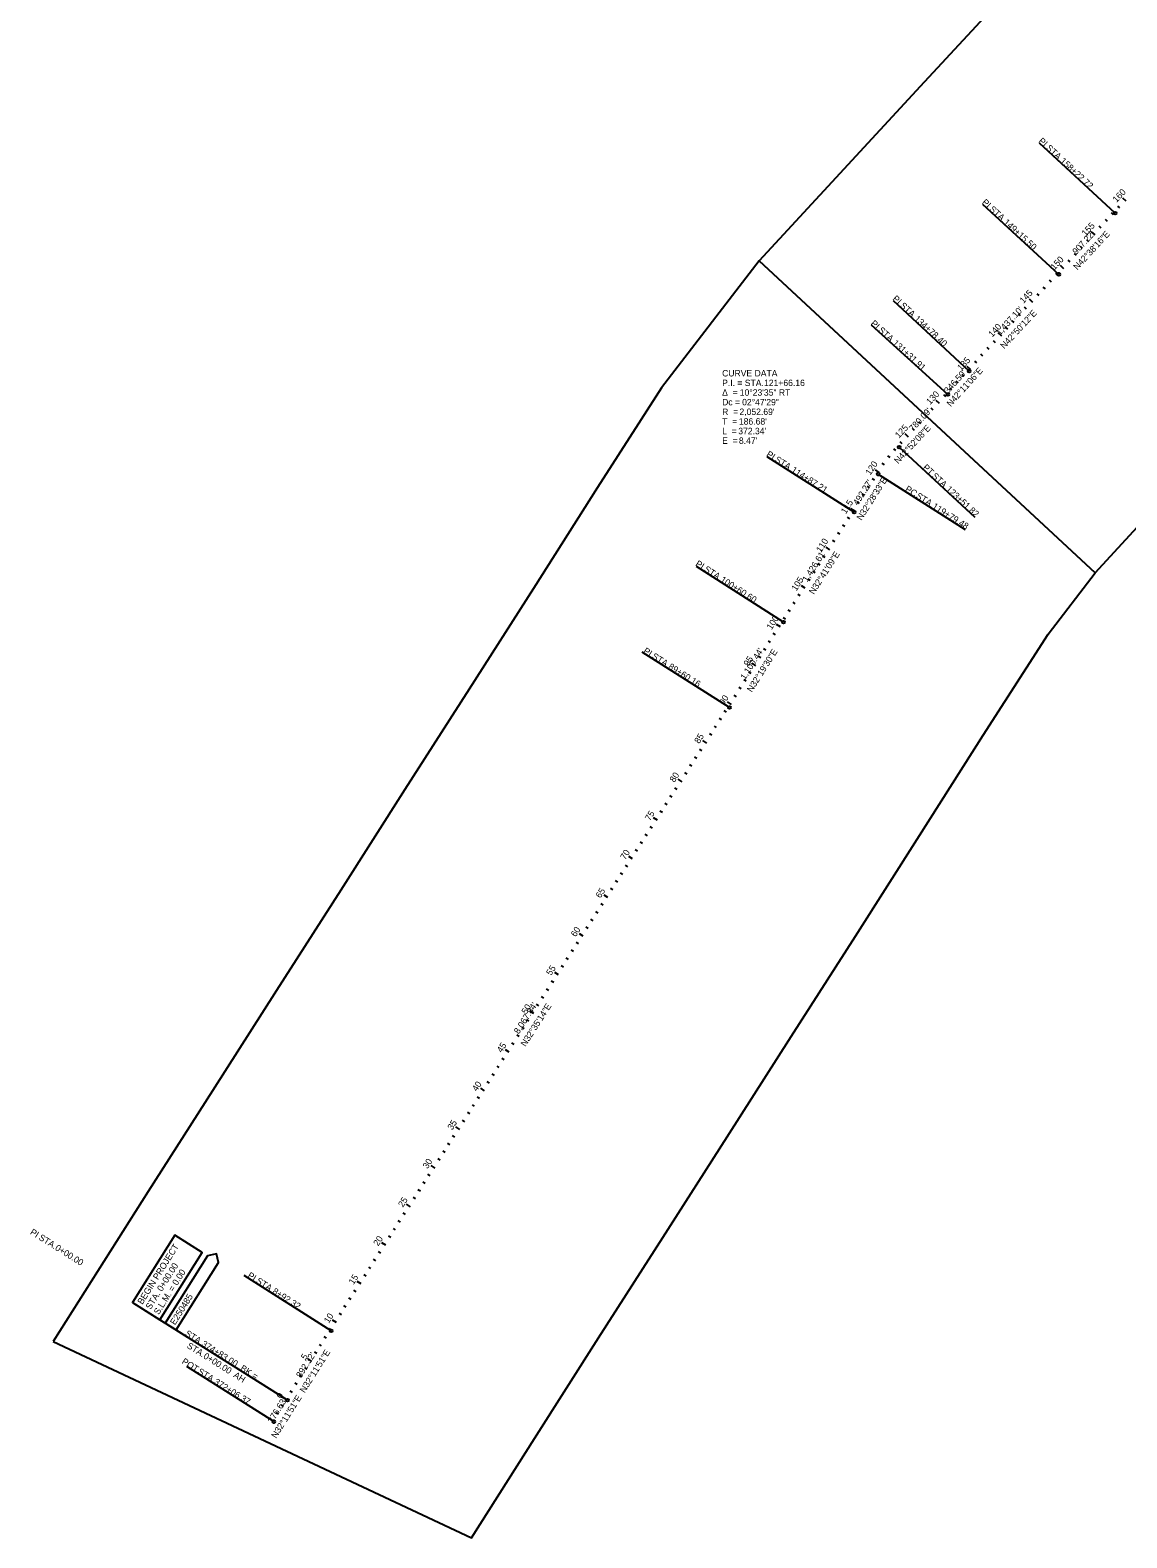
# Model space of a CAD drawing. Extents: x 187058 to 230449, y 263308 to 297406.
# Drawn here: x 187058 to 199019, y 263308 to 279748 of the extents above; entities that cross this region are included whole.
import ezdxf

# ---------------------------------------------------------------- set-up
doc = ezdxf.new("R2010")
doc.units = 0
for name, color, linetype in [('BR_X_Gen_Approach_Slab', 7, 'Continuous'), ('BR_X_SV_Deck_Top', 7, 'Continuous'), ('PV_X_Curb', 7, 'Continuous'), ('PV_X_Walk', 7, 'Continuous'), ('RD_X_GR_Lt', 7, 'Continuous'), ('SH_Named_Boundary', 7, 'Continuous')]:
    doc.layers.add(name, color=color, linetype=linetype)

msp = doc.modelspace()

# ---------------------------------------------------------------- linework, layer by layer
at = {"layer": 'BR_X_SV_Deck_Top'}
for p, q in [((199011, 277882), (198974, 277916)), ((198807, 277662), (198785, 277682)), ((198875, 277735), (198853, 277756)), ((198943, 277809), (198921, 277829)), ((198672, 277515), (198635, 277549)), ((198740, 277588), (198718, 277609)), ((198536, 277368), (198514, 277388)), ((198604, 277441), (198582, 277461)), ((198333, 277147), (198296, 277181)), ((198401, 277220), (198379, 277241)), ((198469, 277294), (198447, 277314)), ((198198, 277000), (198176, 277020)), ((198265, 277073), (198243, 277094)), ((198062, 276853), (198040, 276874)), ((198130, 276927), (198108, 276947)), ((197926, 276707), (197904, 276727)), ((197994, 276780), (197957, 276814)), ((197790, 276560), (197768, 276580)), ((197858, 276633), (197836, 276654)), ((197586, 276340), (197564, 276360)), ((197654, 276413), (197617, 276447)), ((197722, 276487), (197700, 276507)), ((197450, 276193), (197428, 276214)), ((197518, 276267), (197496, 276287)), ((197314, 276047), (197277, 276081)), ((197382, 276120), (197360, 276140)), ((197179, 275899), (197157, 275919)), ((197246, 275973), (197224, 275993)), ((196977, 275677), (196940, 275711)), ((197045, 275751), (197023, 275771)), ((197112, 275825), (197090, 275845)), ((196840, 275531), (196818, 275551)), ((196908, 275604), (196886, 275625)), ((196704, 275384), (196682, 275405)), ((196772, 275458), (196750, 275478)), ((196568, 275238), (196546, 275258)), ((196636, 275311), (196600, 275345)), ((196436, 275087), (196413, 275106)), ((196501, 275164), (196478, 275184)), ((196319, 274925), (196277, 274953)), ((196376, 275008), (196352, 275025)), ((196212, 274757), (196187, 274773)), ((196266, 274841), (196240, 274857)), ((196105, 274588), (196079, 274604)), ((196158, 274672), (196133, 274688)), ((195997, 274419), (195972, 274436)), ((196051, 274504), (196009, 274530)), ((195889, 274251), (195864, 274267)), ((195943, 274335), (195918, 274351)), ((195781, 274083), (195739, 274110)), ((195835, 274167), (195810, 274183)), ((195673, 273914), (195648, 273931)), ((195727, 273999), (195702, 274015)), ((195565, 273746), (195540, 273762)), ((195619, 273830), (195594, 273846)), ((195457, 273578), (195432, 273594)), ((195511, 273662), (195469, 273689)), ((195349, 273409), (195324, 273426)), ((195403, 273494), (195378, 273510)), ((195241, 273241), (195199, 273268)), ((195295, 273325), (195270, 273341)), ((195134, 273072), (195109, 273088)), ((195188, 273156), (195162, 273172)), ((195027, 272903), (195002, 272919)), ((195081, 272987), (195055, 273003)), ((194920, 272734), (194895, 272750)), ((194974, 272818), (194932, 272845)), ((194813, 272565), (194788, 272581)), ((194867, 272649), (194841, 272665)), ((194706, 272396), (194664, 272423)), ((194760, 272480), (194735, 272496)), ((194653, 272312), (194627, 272328)), ((194545, 272143), (194520, 272159)), ((194599, 272227), (194574, 272243)), ((194437, 271975), (194395, 272001)), ((194491, 272059), (194466, 272075)), ((194330, 271806), (194304, 271822)), ((194383, 271890), (194358, 271906)), ((194222, 271637), (194197, 271654)), ((194276, 271722), (194250, 271738)), ((194114, 271469), (194089, 271485)), ((194168, 271553), (194126, 271580)), ((194006, 271300), (193981, 271317)), ((194060, 271385), (194035, 271401)), ((193899, 271132), (193857, 271159)), ((193953, 271216), (193927, 271232)), ((193791, 270963), (193766, 270980)), ((193845, 271048), (193820, 271064)), ((193683, 270795), (193658, 270811)), ((193737, 270879), (193712, 270895)), ((193576, 270626), (193550, 270643)), ((193629, 270711), (193587, 270738)), ((193468, 270458), (193443, 270474)), ((193522, 270542), (193496, 270558)), ((193360, 270289), (193318, 270316)), ((193414, 270374), (193389, 270390)), ((193252, 270121), (193227, 270137)), ((193306, 270205), (193281, 270221)), ((193145, 269952), (193119, 269968)), ((193199, 270037), (193173, 270053)), ((193037, 269784), (193012, 269800)), ((193091, 269868), (193049, 269895)), ((192929, 269615), (192904, 269631)), ((192983, 269700), (192958, 269716)), ((192822, 269447), (192779, 269474)), ((192875, 269531), (192850, 269547)), ((192714, 269278), (192689, 269294)), ((192768, 269363), (192742, 269379)), ((192606, 269110), (192581, 269126)), ((192660, 269194), (192635, 269210)), ((192498, 268941), (192473, 268957)), ((192552, 269026), (192510, 269052)), ((192445, 268857), (192419, 268873)), ((192283, 268604), (192241, 268631)), ((192337, 268688), (192312, 268705)), ((192391, 268773), (192365, 268789)), ((192229, 268520), (192204, 268536)), ((192121, 268351), (192096, 268368)), ((192175, 268436), (192150, 268452)), ((192014, 268183), (191972, 268210)), ((192068, 268267), (192042, 268283)), ((191906, 268014), (191881, 268031)), ((191960, 268099), (191935, 268115)), ((191798, 267846), (191773, 267862)), ((191852, 267930), (191827, 267946)), ((191691, 267677), (191665, 267694)), ((191744, 267762), (191702, 267789)), ((191583, 267509), (191558, 267525)), ((191637, 267593), (191611, 267609)), ((191475, 267340), (191433, 267367)), ((191529, 267425), (191504, 267441)), ((191367, 267172), (191342, 267188)), ((191421, 267256), (191396, 267272)), ((191260, 267003), (191234, 267019)), ((191314, 267088), (191288, 267104)), ((191152, 266835), (191127, 266851)), ((191206, 266919), (191164, 266946)), ((191044, 266666), (191019, 266682)), ((191098, 266751), (191073, 266767)), ((190937, 266498), (190894, 266525)), ((190990, 266582), (190965, 266598)), ((190829, 266329), (190804, 266345)), ((190883, 266414), (190857, 266430)), ((190721, 266161), (190696, 266177)), ((190775, 266245), (190750, 266261)), ((190613, 265992), (190588, 266008)), ((190667, 266076), (190625, 266103)), ((190506, 265824), (190480, 265840)), ((190559, 265908), (190534, 265924)), ((190398, 265655), (190356, 265682)), ((190452, 265739), (190427, 265756)), ((190344, 265571), (190319, 265587)), ((190237, 265402), (190212, 265418)), ((190291, 265486), (190265, 265502)), ((190131, 265232), (190089, 265259)), ((190184, 265317), (190159, 265333)), ((190024, 265063), (189999, 265079)), ((190078, 265148), (190052, 265164)), ((189918, 264894), (189892, 264910)), ((189971, 264979), (189946, 264995)), ((189820, 264739), (189795, 264755)), ((189864, 264809), (189822, 264836)), ((189767, 264655), (189742, 264671))]:
    msp.add_line(p, q, dxfattribs=at)
at = {"layer": 'PV_X_Walk'}
for p, q in [((198891, 277752), (198065, 278516)), ((198276, 277085), (197448, 277847)), ((197299, 276031), (196474, 276796)), ((197066, 275774), (196233, 276530)), ((196044, 274493), (195095, 275097)), ((196536, 275202), (197360, 274437)), ((196308, 274908), (197257, 274304)), ((195274, 273292), (194327, 273900)), ((194685, 272362), (193734, 272964)), ((190340, 265564), (189392, 266170)), ((188175, 265873), (188775, 265495)), ((189864, 264809), (188659, 265569)), ((189864, 264809), (188912, 265409)), ((189717, 264575), (188765, 265175))]:
    msp.add_line(p, q, dxfattribs=at)
msp.add_lwpolyline([(188471, 265687), (188933, 266421), (188637, 266608), (188175, 265873)], close=True, dxfattribs=at)
msp.add_lwpolyline([(188471, 265687), (188649, 265575), (189111, 266309), (189089, 266406), (188993, 266384), (188530, 265650)], dxfattribs=at)
for centre in [(198891, 277752), (198276, 277085), (197299, 276031), (197066, 275774), (196536, 275202), (196308, 274908), (196044, 274493), (195274, 273292), (194685, 272362), (190340, 265564), (189864, 264809), (189864, 264809), (189717, 264575)]:
    msp.add_circle(centre, 15, dxfattribs=at)
at = {"layer": 'SH_Named_Boundary'}
for points in [[(195008, 277232), (198673, 273830), (199555, 274787), (200443, 275748), (201321, 276698), (201882, 277272), (202937, 278024), (203995, 278787), (205049, 279548), (206103, 280310), (207157, 281071), (208205, 281824), (205292, 285888), (204229, 285124), (203175, 284363), (202121, 283601), (201067, 282840), (200017, 282083), (198955, 281325), (197651, 280094), (196765, 279135), (195888, 278186)], [(187308, 265448), (191873, 263308), (192558, 264393), (193258, 265488), (193959, 266584), (194659, 267679), (195359, 268774), (196059, 269870), (196759, 270965), (197453, 272059), (198160, 273161), (198673, 273830), (195008, 277232), (193942, 275846), (193245, 274760), (192546, 273658), (191846, 272563), (191146, 271467), (190446, 270372), (189746, 269277), (189046, 268181), (188345, 267086)]]:
    msp.add_lwpolyline(points, close=True, dxfattribs=at)

# ---------------------------------------------------------------- texts
at = {"layer": 'BR_X_Gen_Approach_Slab'}
for s, rotation, p in [("907.22'", 47.3621, (198469, 277296)), ("1,437.10'", 47.1632, (197634, 276415)), ("346.50'", 47.8149, (197070, 275780)), ("780.09'", 47.1312, (196687, 275367)), ("492.27'", 57.5242, (196086, 274560)), ("1,426.61'", 57.3141, (195533, 273725)), ("1,100.44'", 57.675, (194855, 272659)), ("8,067.84'", 57.4128, (192387, 268796)), ("892.32'", 57.8026, (190012, 265046)), ("276.63'", 57.8026, (189701, 264552))]:
    msp.add_text(s, height=70, rotation=rotation, dxfattribs=at).set_placement(p)
at = {"layer": 'BR_X_SV_Deck_Top'}
for s, rotation, p in [('160', 47.2252, (198908, 277863)), ('155', 47.3621, (198570, 277496)), ('150', 47.3621, (198231, 277128)), ('145', 47.1632, (197892, 276762)), ('140', 47.1632, (197551, 276395)), ('135', 47.1632, (197212, 276029)), ('130', 47.1312, (196874, 275659)), ('125', 47.1312, (196534, 275293)), ('120', 56.9514, (196221, 274889)), ('115', 57.5242, (195954, 274467)), ('110', 57.3141, (195683, 274046)), ('105', 57.3141, (195414, 273626)), ('100', 57.675, (195144, 273204)), ('95', 57.675, (194892, 272806)), ('90', 57.675, (194624, 272382)), ('85', 57.4128, (194355, 271962)), ('80', 57.4128, (194085, 271540)), ('75', 57.4128, (193817, 271120)), ('70', 57.4128, (193547, 270697)), ('65', 57.4128, (193278, 270277)), ('60', 57.4128, (193008, 269855)), ('55', 57.4128, (192739, 269434)), ('50', 57.4128, (192470, 269012)), ('45', 57.4128, (192201, 268592)), ('40', 57.4128, (191931, 268170)), ('35', 57.4128, (191662, 267749)), ('30', 57.4128, (191392, 267327)), ('25', 57.4128, (191124, 266907)), ('20', 57.4128, (190854, 266484)), ('15', 57.4128, (190585, 266064)), ('10', 57.4128, (190315, 265642)), ('5', 57.8026, (190064, 265243)), ('0', 57.8026, (189797, 264819))]:
    msp.add_text(s, height=70, rotation=rotation, dxfattribs=at).set_placement(p)
at = {"layer": 'PV_X_Curb'}
for s, p in [('CURVE DATA', (194605, 275972)), ('P.I. = STA. ', (194605, 275867)), ('121+66.16', (195062, 275867)), ('Δ  = ', (194605, 275762)), ('Dc = ', (194605, 275657)), ('10°23\'35" RT', (194797, 275762)), ('02°47\'29"', (194823, 275657)), ('R  = ', (194605, 275552)), ("2,052.69'", (194794, 275552)), ('T  = ', (194605, 275447)), ('L  = ', (194605, 275342)), ("372.34'", (194781, 275342)), ("186.68'", (194788, 275447)), ('E  = ', (194605, 275237)), ("8.47'", (194788, 275237))]:
    msp.add_text(s, height=70, dxfattribs=at).set_placement(p)
at = {"layer": 'PV_X_Walk'}
for s, rotation, p in [('PI', 317.2252, (198050, 278531)), (' STA. ', 317.2252, (198113, 278473)), ('158+22.72', 317.2252, (198286, 278313)), ('PI', 317.3621, (197433, 277863)), (' STA. ', 317.3621, (197495, 277805)), ('149+15.50', 317.3621, (197669, 277645)), ('PI', 317.1632, (196458, 276812)), (' STA. ', 317.1632, (196520, 276754)), ('PI', 317.8149, (196220, 276542)), ('134+78.40', 317.1632, (196694, 276593)), (' STA. ', 317.8149, (196283, 276485)), ('131+31.91', 317.8149, (196458, 276327)), ('PI', 327.5242, (195081, 275107)), (' STA. ', 327.5242, (195152, 275062)), ('114+87.21', 327.5242, (195352, 274935)), ('PT', 317.1312, (196787, 274971)), (' STA. ', 317.1312, (196867, 274896)), ('PC', 327.5242, (196594, 274727)), ('123+51.82', 317.1312, (197041, 274735)), (' STA. ', 327.5242, (196691, 274666)), ('119+79.48', 327.5242, (196890, 274539)), ('PI', 327.3141, (194308, 273913)), (' STA. ', 327.3141, (194380, 273867)), ('100+60.60', 327.3141, (194579, 273739)), ('PI', 327.675, (193739, 272962)), (' STA. ', 327.675, (193811, 272917)), ('89+60.16', 327.675, (194011, 272790)), ('PI', 327.8026, (187051, 266624)), (' STA. ', 327.8026, (187123, 266579)), ('0+00.00', 327.8026, (187323, 266453)), ('BEGIN PROJECT', 57.8026, (188282, 265847)), ('STA. 0+00.00', 57.8026, (188371, 265791)), ('S.L.M. = 0.00', 57.8026, (188460, 265735)), ('PI', 327.4128, (189422, 266152)), (' STA. ', 327.4128, (189494, 266107)), ('8+92.32', 327.4128, (189693, 265979)), ('E250485', 57.8026, (188638, 265623)), ('STA. ', 327.8026, (188741, 265518)), ('STA. ', 327.8026, (188761, 265385)), ('374+83.00', 327.8026, (188920, 265405)), ('POT', 327.8026, (188705, 265214)), ('0+00.00', 327.8026, (188940, 265272)), (' BK =', 327.8026, (189321, 265153)), (' STA. ', 327.8026, (188857, 265118)), ('372+06.37', 327.8026, (189057, 264992)), (' AH', 327.8026, (189246, 265079))]:
    msp.add_text(s, height=70, rotation=rotation, dxfattribs=at).set_placement(p)
at = {"layer": 'RD_X_GR_Lt'}
for s, rotation, p in [('N42°38\'16"E', 47.3621, (198479, 277128)), ('N42°50\'12"E', 47.1632, (197682, 276268)), ('N42°11\'06"E', 47.8149, (197098, 275637)), ('N42°52\'08"E', 47.1312, (196525, 275014)), ('N32°28\'33"E', 57.5242, (196125, 274396)), ('N32°41\'09"E', 57.3141, (195606, 273589)), ('N32°19\'30"E', 57.675, (194929, 272523)), ('N32°35\'14"E', 57.4128, (192461, 268659)), ('N32°11\'51"E', 57.8026, (190052, 264883)), ('N32°11\'51"E', 57.8026, (189741, 264388))]:
    msp.add_text(s, height=70, rotation=rotation, dxfattribs=at).set_placement(p)

doc.saveas('drawing.dxf')
